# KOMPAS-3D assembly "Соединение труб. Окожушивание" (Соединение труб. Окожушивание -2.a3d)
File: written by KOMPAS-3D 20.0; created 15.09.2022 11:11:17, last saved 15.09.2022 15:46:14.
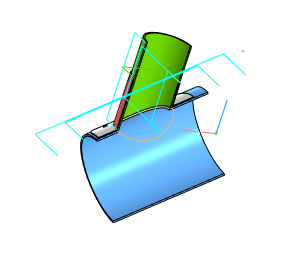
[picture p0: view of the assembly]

Document properties: Полное имя файла: D:\YAKOVLEV\ПРОЕКТЫ\ДЦ-2. ДП-7 Газопровод Окожушивание\ПРОБА Соединение труб. Окожушивание\Соединение труб. Окожушивание -2.a3d

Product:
- Part/product: Соединение труб. Окожушивание
    Масса: 7430.06
  - Component [detail]: Кожух 2 (вставки)  | Материал: Сталь 45  ГОСТ 1050-2013 (density 7810 kg/m3); Масса: 382.706; source file: Кожух 2 (вставки).m3d.bak
  - Component [detail]: Кожух 2 (вставки) сек.В  | Материал: Сталь 45  ГОСТ 1050-2013 (density 7810 kg/m3); Масса: 153.628; source file: Кожух 2 (вставки) сек.В.m3d
  - Component [detail]: Кожух 2 (вставки) сек.Б  | Материал: Сталь 45  ГОСТ 1050-2013 (density 7810 kg/m3); Масса: 153.619; source file: Кожух 2 (вставки) сек.Б.m3d
  - Component [detail]: Кожух 2 (вставки) сек.А  | Материал: Сталь 45  ГОСТ 1050-2013 (density 7810 kg/m3); Масса: 73.9329; source file: Кожух 2 (вставки) сек.А.m3d
  - Component [detail]: Кожух 1 (трубы)  | Материал: Сталь 45  ГОСТ 1050-2013 (density 7810 kg/m3); Масса: 419.401; source file: Кожух 1 (трубы).m3d
  - Component [detail]: Кожух 1 (трубы) СЕКТОР 3  | Материал: Сталь 45  ГОСТ 1050-2013 (density 7810 kg/m3); Масса: 116.939; source file: Кожух 1 (трубы) СЕКТОР 4.m3d
  - Component [detail]: Кожух 1 (трубы) СЕКТОР 2  | Материал: Сталь 45  ГОСТ 1050-2013 (density 7810 kg/m3); Масса: 92.2939; source file: Кожух 1 (трубы) СЕКТОР 2.m3d
  - Component [assembly]: Соединение труб  | Масса: 5828.65; source file: Соединение труб.a3d
  - Component [detail]: Кожух 1 (трубы) СЕКТОР 3  | Материал: Сталь 45  ГОСТ 1050-2013 (density 7810 kg/m3); Масса: 116.573; source file: Кожух 1 (трубы) СЕКТОР 3.m3d
  - Component [detail]: Кожух 1 (трубы) СЕКТОР 1  | Материал: Сталь 45  ГОСТ 1050-2013 (density 7810 kg/m3); Масса: 92.321; source file: Кожух 1 (трубы) СЕКТОР 1.m3d

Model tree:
1. Смещенная плоскость:1  (with: Обечайка:1)
     Расстояние = 800; Ориентация = 2; Ориентация = 2

Referenced files in D:\YAKOVLEV\ПРОЕКТЫ\ДЦ-2. ДП-7 Газопровод Окожушивание\ПРОБА Соединение труб. Окожушивание\: Соединение труб.a3d, Кожух 1 (трубы) СЕКТОР 2.m3d, Кожух 1 (трубы) СЕКТОР 1.m3d, Кожух 1 (трубы) СЕКТОР 3.m3d, Кожух 1 (трубы) СЕКТОР 4.m3d, Кожух 1 (трубы).m3d, Кожух 2 (вставки) сек.А.m3d, Кожух 2 (вставки) сек.Б.m3d, Кожух 2 (вставки) сек.В.m3d, Кожух 2 (вставки).m3d.bak
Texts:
  Точка начала. Х
  Точка начала. Y
  Точка начала. Z
  Кожух 2 (вставки).m3d.bak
